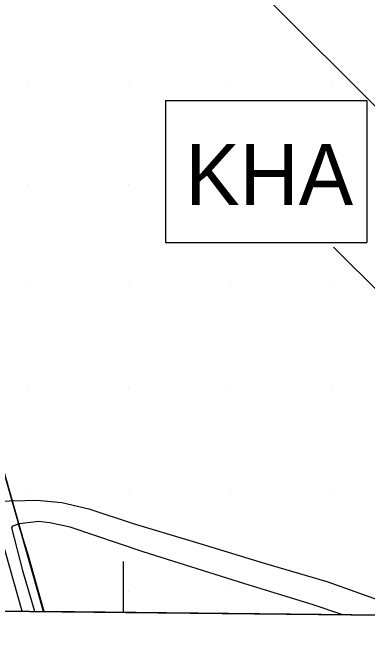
# Model space of a CAD drawing. Extents: x 417995 to 421451, y 4454518 to 4458015.
# Drawn here: x 420472.7 to 420559.9, y 4454999.4 to 4455155 of the extents above; entities that cross this region are included whole.
import ezdxf

# ---------------------------------------------------------------- set-up
doc = ezdxf.new("R2010")
doc.units = 0
for name, color, linetype in [('ADAKENARI', 7, 'Continuous'), ('KALDIRIM_FAT', 7, 'Continuous'), ('P_Grid', 7, 'Continuous'), ('PAFTALAMA', 7, 'Continuous'), ('PL_KAMU_HİZMET_ALANI', 7, 'Continuous'), ('SEMBOL_FAT', 7, 'Continuous'), ('SN_TR_SIVILASMA', 7, 'Continuous'), ('TRFAT_KHA', 7, 'Continuous'), ('Y_Lejant', 7, 'Continuous'), ('Yol_Kaldirim_kenari_bordurtasi', 7, 'Continuous'), ('Yol_Sose', 7, 'Continuous'), ('Yol_Toprak_Duz', 7, 'Continuous'), ('Yol_Toprak_Kesik', 7, 'Continuous')]:
    doc.layers.add(name, color=color, linetype=linetype)

msp = doc.modelspace()

# ---------------------------------------------------------------- linework, layer by layer
at = {"layer": 'ADAKENARI'}
msp.add_line((420480.29, 4455007.71), (420460.48, 4455077.61), dxfattribs=at)
at = {"layer": 'KALDIRIM_FAT'}
msp.add_line((420475.08, 4455007.77), (420455.58, 4455076.59), dxfattribs=at)
at = {"layer": 'P_Grid'}
msp.add_line((420500, 4455007.5), (420500, 4455020), dxfattribs=at)
at = {"layer": 'PAFTALAMA'}
msp.add_line((419138.44, 4455021.89), (421266.41, 4454999.4), dxfattribs=at)
at = {"layer": 'PL_KAMU_HİZMET_ALANI'}
for p, q in [((420480.29, 4455007.71), (420608.01, 4455006.36)), ((420608.01, 4455006.36), (420480.29, 4455007.71))]:
    msp.add_line(p, q, dxfattribs=at)
msp.add_lwpolyline([(420608.01, 4455006.36), (420610.24, 4455191.26), (420611.77, 4455234.39), (420452.99, 4455236.3), (420451.28, 4455217.73), (420451.44, 4455146.33), (420454.49, 4455123.19), (420460.48, 4455077.61), (420480.29, 4455007.71)], dxfattribs=at)
at = {"layer": 'SEMBOL_FAT'}
for p, q in [((420510.29, 4455133.47), (420510.29, 4455098.47)), ((420510.29, 4455133.47), (420559.76, 4455133.47)), ((420559.76, 4455133.47), (420559.76, 4455098.47)), ((420510.29, 4455098.47), (420559.76, 4455098.47))]:
    msp.add_line(p, q, dxfattribs=at)
at = {"layer": 'SN_TR_SIVILASMA'}
for p, q in [((420688.32, 4455005.51), (420489.88, 4455203.95)), ((420642.94, 4455005.99), (420551.62, 4455097.32))]:
    msp.add_line(p, q, dxfattribs=at)
at = {"layer": 'TRFAT_KHA'}
for p, q in [((420476.28, 4455137.74), (420476.28, 4455137.74)), ((420501.28, 4455137.74), (420501.28, 4455137.74)), ((420526.28, 4455137.74), (420526.28, 4455137.74)), ((420551.28, 4455137.74), (420551.28, 4455137.74)), ((420476.28, 4455112.74), (420476.28, 4455112.74)), ((420501.28, 4455112.74), (420501.28, 4455112.74)), ((420526.28, 4455112.74), (420526.28, 4455112.74)), ((420551.28, 4455112.74), (420551.28, 4455112.74)), ((420476.28, 4455087.74), (420476.28, 4455087.74)), ((420501.28, 4455087.74), (420501.28, 4455087.74)), ((420526.28, 4455087.74), (420526.28, 4455087.74)), ((420551.28, 4455087.74), (420551.28, 4455087.74)), ((420476.28, 4455062.74), (420476.28, 4455062.74)), ((420501.28, 4455062.74), (420501.28, 4455062.74)), ((420526.28, 4455062.74), (420526.28, 4455062.74)), ((420551.28, 4455062.74), (420551.28, 4455062.74)), ((420476.28, 4455037.74), (420476.28, 4455037.74)), ((420501.28, 4455037.74), (420501.28, 4455037.74)), ((420526.28, 4455037.74), (420526.28, 4455037.74)), ((420551.28, 4455037.74), (420551.28, 4455037.74)), ((420501.28, 4455012.74), (420501.28, 4455012.74)), ((420526.28, 4455012.74), (420526.28, 4455012.74)), ((420551.28, 4455012.74), (420551.28, 4455012.74))]:
    msp.add_line(p, q, dxfattribs=at)
at = {"layer": 'Y_Lejant'}
msp.add_lwpolyline([(419168.18, 4457798.01), (421295.36, 4457775.52), (421266.41, 4454999.4), (419138.44, 4455021.89)], close=True, dxfattribs=at)
at = {"layer": 'Yol_Kaldirim_kenari_bordurtasi'}
msp.add_lwpolyline([(420480.45, 4455007.71), (420476.5, 4455022.03), (420474.21, 4455029.24)], dxfattribs=at)
at = {"layer": 'Yol_Sose'}
for points in [[(420458.18, 4455078.14), (420462.61, 4455061.83), (420470.43, 4455035.03), (420470.83, 4455034.87), (420472.97, 4455035)], [(420474.44, 4455029.32), (420472.74, 4455028.71), (420472.52, 4455028.5), (420472.44, 4455028.29), (420475.2, 4455017.82), (420477.88, 4455008.59), (420478.1, 4455007.73)]]:
    msp.add_lwpolyline(points, dxfattribs=at)
at = {"layer": 'Yol_Toprak_Duz'}
msp.add_lwpolyline([(420553.9, 4455006.93), (420546.38, 4455009.43), (420529.84, 4455014.54), (420504.8, 4455022.41), (420486.84, 4455028.5), (420481.91, 4455029.58), (420479.08, 4455029.86), (420474.44, 4455029.32)], dxfattribs=at)
at = {"layer": 'Yol_Toprak_Kesik'}
msp.add_lwpolyline([(420472.87, 4455034.99), (420478.67, 4455035.11), (420484.85, 4455034.52), (420491.46, 4455032.96), (420502.32, 4455029.35), (420518.77, 4455024.49), (420534.54, 4455019.6), (420549.96, 4455015.08), (420563.71, 4455010.19), (420571.85, 4455006.94), (420572.46, 4455006.74)], dxfattribs=at)

# ---------------------------------------------------------------- texts
at = {"layer": 'SEMBOL_FAT'}
msp.add_text('KHA', height=15, dxfattribs=at).set_placement((420515.18, 4455107.7))

doc.saveas('drawing.dxf')
